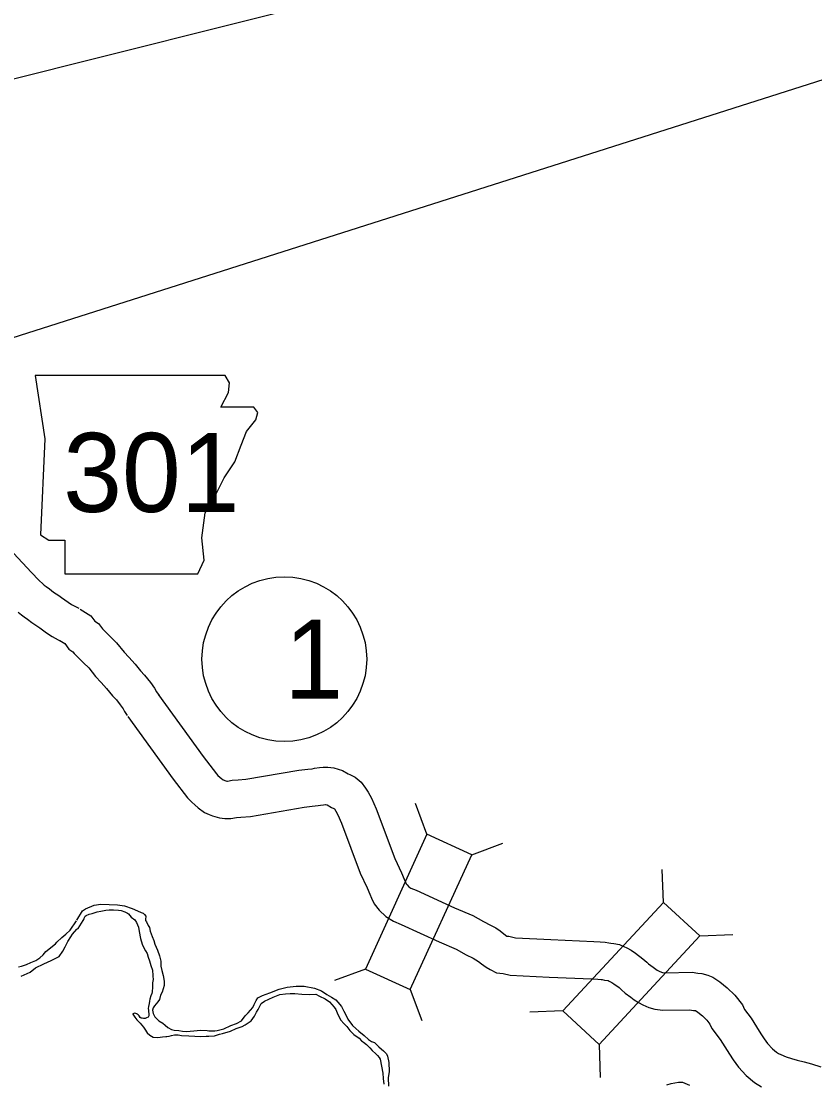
# Model space of a CAD drawing. Extents: x 79818 to 83933, y 50884 to 53307.
# Drawn here: x 81078.5 to 81163.3, y 52994.1 to 53107.7 of the extents above; entities that cross this region are included whole.
import ezdxf

# ---------------------------------------------------------------- set-up
doc = ezdxf.new("R2010")
doc.units = 0
for name, color, linetype in [('Default', 7, 'Continuous'), ('Level 10', 7, 'Continuous'), ('Level 20', 7, 'Continuous'), ('Level 21', 7, 'Continuous'), ('Level 27', 7, 'Continuous'), ('Level 9', 7, 'Continuous')]:
    doc.layers.add(name, color=color, linetype=linetype)

msp = doc.modelspace()

# ---------------------------------------------------------------- linework, layer by layer
at = {"layer": 'Default'}
for p in [(81049.64, 53094.55), (81071.88, 53072.06)]:
    msp.add_line(p, (81483.45, 53203.33), dxfattribs=at)
at = {"layer": 'Level 10'}
for points in [[(81076.23, 53052.4), (81079.64, 53048.78), (81080.41, 53047.98), (81080.86, 53047.53), (81080.99, 53047.43), (81081.18, 53047.28), (81081.55, 53047.04), (81081.99, 53046.69), (81082.54, 53046.33), (81082.83, 53046.13), (81083.54, 53045.62), (81083.89, 53045.38), (81084.68, 53044.96)], [(81078.21, 53044.53), (81078.54, 53044.27), (81078.85, 53044.03), (81079.21, 53043.79), (81079.65, 53043.44), (81080.3, 53043.01), (81080.53, 53042.86), (81081.24, 53042.35), (81081.82, 53041.95), (81082.81, 53041.42)], [(81084.81, 53044.88), (81085.95, 53044.16), (81086.39, 53043.57), (81086.78, 53043.32), (81087.2, 53042.77), (81087.99, 53041.98), (81088.72, 53041.26), (81089.51, 53040.27), (81090.01, 53039.73), (81090.7, 53038.98), (81091.26, 53038.27), (81091.71, 53037.82), (81092.33, 53037.02), (81092.76, 53036.41), (81092.99, 53036.03), (81093.25, 53035.62)], [(81082.67, 53041.5), (81083.17, 53041.18), (81083.62, 53040.58), (81084.03, 53040.32), (81084.18, 53040.13), (81085.18, 53039.14), (81085.74, 53038.58), (81086.48, 53037.65), (81087.08, 53037.02), (81087.65, 53036.39), (81088.27, 53035.6), (81088.7, 53035.17), (81089.11, 53034.65), (81089.41, 53034.22), (81089.58, 53033.93), (81089.86, 53033.49)], [(81093.18, 53035.72), (81097.96, 53029.1), (81099.38, 53027.27), (81099.55, 53027.08), (81099.75, 53026.91), (81099.95, 53026.73), (81100.08, 53026.63), (81100.13, 53026.61), (81100.27, 53026.56), (81100.5, 53026.49), (81100.58, 53026.49), (81101.08, 53026.57), (81101.71, 53026.62), (81102.51, 53026.68), (81108.2, 53027.66), (81109.15, 53027.76), (81109.6, 53027.81), (81109.88, 53027.87), (81110.39, 53027.93), (81110.78, 53027.97), (81111.28, 53027.98), (81111.93, 53027.91), (81112.84, 53027.6), (81113.47, 53027.25), (81113.63, 53027.18), (81114.21, 53026.89), (81114.86, 53026.38), (81115.32, 53025.74), (81115.6, 53025.29), (81115.96, 53024.65), (81116.46, 53023.5), (81118.43, 53018.21), (81119.15, 53016.68), (81119.43, 53015.99), (81119.57, 53015.67), (81119.66, 53015.5), (81119.76, 53015.38), (81119.95, 53015.19), (81120.17, 53015.05), (81120.74, 53014.81), (81124.81, 53012.95), (81126.77, 53012.1), (81127.92, 53011.46), (81128.68, 53011.09), (81129.22, 53010.78), (81129.69, 53010.46), (81130.1, 53010.16), (81130.43, 53009.91), (81130.64, 53009.9), (81131.35, 53009.73), (81135.11, 53009.53), (81139.7, 53009.34), (81140.38, 53009.3), (81140.92, 53009.26), (81141.31, 53009.2), (81141.52, 53009.16), (81141.86, 53009.11), (81142.44, 53009), (81142.93, 53008.79), (81143.22, 53008.64), (81143.68, 53008.4), (81144.15, 53008.08), (81144.96, 53007.49), (81145.37, 53007.11), (81145.56, 53006.93), (81146.03, 53006.6), (81146.35, 53006.36), (81146.48, 53006.27), (81146.68, 53006.17), (81146.92, 53006.06), (81147.03, 53006.03), (81147.34, 53005.99), (81150.21, 53006.04), (81150.81, 53005.94), (81151.26, 53005.91), (81151.89, 53005.72), (81152.42, 53005.51), (81153.18, 53005.01), (81153.97, 53004.37), (81154.76, 53003.61), (81155.58, 53002.57), (81155.8, 53002.07), (81156.53, 53001.12), (81157.08, 53000.21), (81157.56, 52999.47), (81157.92, 52998.93), (81158.27, 52998.43), (81158.79, 52997.87), (81159.21, 52997.51), (81159.45, 52997.36), (81159.67, 52997.27), (81160.27, 52997.02), (81160.83, 52996.83), (81161.43, 52996.66), (81162.19, 52996.48), (81162.98, 52996.26), (81163.95, 52995.93)], [(81089.93, 53033.38), (81094.76, 53026.7), (81096.31, 53024.69), (81096.74, 53024.22), (81097.08, 53023.93), (81097.43, 53023.61), (81098.11, 53023.13), (81098.6, 53022.92), (81098.97, 53022.77), (81099.7, 53022.56), (81100.28, 53022.49), (81100.94, 53022.5), (81101.54, 53022.6), (81102, 53022.63), (81103.01, 53022.7), (81108.76, 53023.7), (81109.6, 53023.79), (81110.24, 53023.86), (81110.52, 53023.92), (81110.84, 53023.96), (81111.03, 53023.98), (81111.07, 53023.98), (81111.2, 53023.93), (81111.67, 53023.67), (81111.92, 53023.56), (81111.99, 53023.52), (81112.15, 53023.26), (81112.37, 53022.86), (81112.76, 53022), (81114.74, 53016.65), (81115.49, 53015.07), (81115.76, 53014.41), (81115.95, 53013.98), (81116.25, 53013.36), (81116.78, 53012.69), (81117.48, 53012.01), (81118.32, 53011.49), (81119.12, 53011.15), (81123.18, 53009.3), (81125, 53008.5), (81126.06, 53007.92), (81126.81, 53007.55), (81127.11, 53007.38), (81127.39, 53007.18), (81127.71, 53006.95), (81128.2, 53006.58), (81128.62, 53006.34), (81129.3, 53005.98), (81130.03, 53005.93), (81130.77, 53005.75), (81134.93, 53005.53), (81139.49, 53005.35), (81140.12, 53005.31), (81140.49, 53005.28), (81140.59, 53005.27), (81140.83, 53005.21), (81141.21, 53005.16), (81141.25, 53005.16), (81141.36, 53005.1), (81141.63, 53004.96), (81141.86, 53004.8), (81142.41, 53004.4), (81142.65, 53004.18), (81143.05, 53003.81), (81143.66, 53003.38), (81144.02, 53003.1), (81144.48, 53002.8), (81144.96, 53002.56), (81145.58, 53002.28), (81146.23, 53002.11), (81147.09, 53001.99), (81149.92, 53002.04), (81150.36, 53001.97), (81150.53, 53001.95), (81150.56, 53001.95), (81150.82, 53001.77), (81151.32, 53001.37), (81151.79, 53000.92), (81152.11, 53000.51), (81152.32, 53000.02), (81153.22, 52998.86), (81153.69, 52998.07), (81154.22, 52997.28), (81154.61, 52996.68), (81155.16, 52995.91), (81156, 52994.99), (81156.86, 52994.25), (81157.61, 52993.8)]]:
    msp.add_lwpolyline(points, dxfattribs=at)
at = {"layer": 'Level 20'}
for p, q in [((81121.87, 53020.8), (81120.64, 53024.1)), ((81126.67, 53018.61), (81129.97, 53019.84)), ((81147.16, 53013.52), (81147.02, 53017.04)), ((81151.03, 53009.93), (81154.55, 53010.07)), ((81115.3, 53006.39), (81112, 53005.15)), ((81120.1, 53004.2), (81121.33, 53000.9)), ((81136.39, 53001.91), (81132.87, 53001.77)), ((81140.26, 52998.32), (81140.39, 52994.8))]:
    msp.add_line(p, q, dxfattribs=at)
for points in [[(81120.1, 53004.2), (81126.67, 53018.61), (81121.87, 53020.8), (81115.3, 53006.39)], [(81147.16, 53013.52), (81136.39, 53001.91), (81140.26, 52998.32), (81151.03, 53009.93)]]:
    msp.add_lwpolyline(points, close=True, dxfattribs=at)
at = {"layer": 'Level 21'}
msp.add_lwpolyline([(81080.02, 53069.85), (81081.04, 53063.08), (81080.59, 53052.81), (81081.49, 53052.25), (81083.18, 53052.25), (81083.18, 53048.64), (81097.39, 53048.64), (81098.07, 53050.11), (81097.84, 53052.48), (81098.18, 53055.18), (81099.42, 53057.33), (81100.21, 53058.91), (81101.34, 53060.6), (81102.01, 53062.4), (81102.58, 53063.87), (81103.59, 53065.11), (81103.82, 53065.9), (81103.37, 53066.46), (81099.87, 53066.46), (81100.66, 53068.04), (81100.77, 53069.06), (81100.31, 53069.84)], close=True, dxfattribs=at)
at = {"layer": 'Level 27'}
msp.add_circle((81106.64, 53039.52), 8.8, dxfattribs=at)
at = {"layer": 'Level 9'}
for points in [[(81084.46, 53011.6), (81085.09, 53012.61), (81085.39, 53012.83), (81086.31, 53013.21), (81087.03, 53013.31), (81087.94, 53013.3), (81088.83, 53013.27), (81089.58, 53013.16), (81090.38, 53012.85), (81090.94, 53012.62), (81091.36, 53012.44), (81091.55, 53012.35), (81091.71, 53012.23), (81091.84, 53012.05), (81091.83, 53011.92), (81091.79, 53011.81), (81091.79, 53011.76), (81091.81, 53011.59), (81091.91, 53011.45), (81092.1, 53011.06), (81092.24, 53010.83), (81092.31, 53010.45), (81092.51, 53009.87), (81092.68, 53009.43), (81092.8, 53009.05), (81093.1, 53008.42), (81093.3, 53007.79), (81093.43, 53007.23), (81093.44, 53006.71), (81093.56, 53006.22), (81093.71, 53005.69), (81093.79, 53005.11), (81093.79, 53004.63), (81093.69, 53004.26), (81093.57, 53003.92), (81093.42, 53003.58), (81093.31, 53003.13), (81093.13, 53002.88), (81092.93, 53002.68), (81092.76, 53002.45), (81092.62, 53002.23), (81092.57, 53002.01), (81092.62, 53001.64), (81092.79, 53001.28), (81093.23, 53000.86), (81093.65, 53000.6), (81093.91, 53000.39), (81094.19, 53000.15), (81094.59, 52999.94), (81094.88, 52999.85), (81095.35, 52999.81), (81095.76, 52999.76), (81096.17, 52999.71), (81096.96, 52999.77), (81097.68, 52999.86), (81098.41, 52999.83), (81098.58, 52999.8), (81099.22, 52999.8), (81099.46, 52999.83), (81100.16, 53000.01), (81100.92, 53000.35), (81101.52, 53000.58), (81102.06, 53000.86), (81102.45, 53001.4), (81102.77, 53001.7), (81103.27, 53002.28), (81103.43, 53002.59), (81103.62, 53003.02), (81103.81, 53003.3), (81104.32, 53003.56), (81105.1, 53003.86), (81106.08, 53004.22), (81106.96, 53004.46), (81107.92, 53004.56), (81108.22, 53004.56), (81108.76, 53004.56), (81109.87, 53004.34), (81110.61, 53004.06), (81111.19, 53003.65), (81111.67, 53003.39), (81112.14, 53003.08), (81112.35, 53002.84), (81112.76, 53002.37), (81112.98, 53001.9), (81113.25, 53001.42), (81113.42, 53001.03), (81113.91, 53000.36), (81114.29, 53000.03), (81114.6, 52999.75), (81115.17, 52999.29), (81115.64, 52998.86), (81115.97, 52998.65), (81116.26, 52998.52), (81116.73, 52998.08), (81117.02, 52997.81), (81117.25, 52997.66), (81117.55, 52997.34), (81117.67, 52997.07), (81117.8, 52996.39), (81117.83, 52995.44)], [(81084.62, 53010.71), (81085.15, 53011.58), (81085.24, 53011.75), (81085.28, 53011.89), (81085.36, 53012.05), (81085.48, 53012.13), (81085.78, 53012.26), (81086.1, 53012.34), (81086.65, 53012.49), (81087.05, 53012.56), (81087.56, 53012.69), (81087.91, 53012.72), (81088.39, 53012.71), (81088.92, 53012.7), (81089.19, 53012.66), (81089.6, 53012.51), (81089.87, 53012.36), (81090, 53012.29), (81090.29, 53011.95), (81090.66, 53011.66), (81090.85, 53011.38), (81091.06, 53010.88), (81091.14, 53010.4), (81091.28, 53009.65), (81091.45, 53009.06), (81091.61, 53008.74), (81091.82, 53008.32), (81091.99, 53008.05), (81092.08, 53007.65), (81092.23, 53007.27), (81092.38, 53006.78), (81092.54, 53006.26), (81092.55, 53006.1), (81092.59, 53005.88), (81092.58, 53005.61), (81092.61, 53005.28), (81092.57, 53004.92), (81092.54, 53004.44), (81092.51, 53003.97), (81092.5, 53003.77), (81092.39, 53003.54), (81092.28, 53003.18), (81092.24, 53002.97), (81092.2, 53002.71), (81092.13, 53002.39), (81092.1, 53002.18), (81092.13, 53001.98), (81092.14, 53001.8), (81092.15, 53001.64), (81092.15, 53001.39), (81092.08, 53001.25), (81091.92, 53001.16), (81091.77, 53001.11), (81091.6, 53001.1), (81091.45, 53001.14), (81091.36, 53001.15), (81091.23, 53001.22), (81091.12, 53001.38), (81091.05, 53001.47), (81091.01, 53001.51), (81090.93, 53001.58), (81090.87, 53001.61), (81090.76, 53001.63), (81090.6, 53001.66), (81090.55, 53001.65), (81090.44, 53001.6), (81090.44, 53001.58), (81090.52, 53001.45), (81090.65, 53001.26), (81090.88, 53000.97), (81091.22, 53000.6), (81091.58, 53000.19), (81091.75, 52999.97), (81091.98, 52999.58), (81092.26, 52999.33), (81092.63, 52999.11), (81093.11, 52999.08), (81093.62, 52999.13), (81093.99, 52999.16), (81094.1, 52999.16), (81094.34, 52999.22), (81094.59, 52999.3), (81094.9, 52999.35), (81095.29, 52999.34), (81095.65, 52999.27), (81096.42, 52999.25), (81097.07, 52999.22), (81097.72, 52999.18), (81098.29, 52999.2), (81098.58, 52999.21), (81099.18, 52999.26), (81099.71, 52999.41), (81100.03, 52999.5), (81100.89, 52999.74), (81101.51, 53000.02), (81102.14, 53000.25), (81102.47, 53000.41), (81103.08, 53000.86), (81103.44, 53001.36), (81103.67, 53001.77), (81103.83, 53002.06)], [(81078.24, 53006.61), (81078.57, 53006.71), (81079.08, 53006.87), (81079.57, 53007.09), (81080.1, 53007.32), (81080.51, 53007.57), (81080.89, 53007.92), (81081.15, 53008.25), (81082.19, 53009.09), (81082.34, 53009.25), (81082.86, 53009.77), (81083.31, 53010.1), (81083.74, 53010.54), (81084.44, 53011.56)], [(81078.53, 53005.63), (81079.49, 53006.07), (81080.06, 53006.53), (81080.93, 53006.96), (81081.72, 53007.32), (81082.57, 53007.74), (81082.99, 53008.29), (81083.23, 53008.75), (81083.52, 53009.32), (81083.83, 53009.84), (81084.02, 53010.12), (81084.46, 53010.65), (81084.62, 53010.71)], [(81103.83, 53002.06), (81104.18, 53002.69), (81104.51, 53002.96), (81105, 53003.17), (81105.44, 53003.38), (81106.15, 53003.67), (81106.78, 53003.74), (81107.28, 53003.79), (81107.76, 53003.77), (81108.51, 53003.71), (81109.28, 53003.67), (81110.01, 53003.69), (81110.41, 53003.48), (81110.99, 53003.19), (81111.48, 53002.88), (81111.96, 53002.33), (81112.13, 53002.06), (81112.29, 53001.7), (81112.51, 53001.25), (81112.68, 53000.94), (81113, 53000.56), (81113.32, 53000.24), (81113.65, 52999.83), (81114.08, 52999.38), (81114.63, 52999), (81114.9, 52998.73), (81115.09, 52998.58), (81115.42, 52998.33), (81115.78, 52997.96), (81116.04, 52997.68), (81116.43, 52997.32), (81116.59, 52997.16), (81116.76, 52996.92), (81116.89, 52996.75), (81117.18, 52995.24), (81117.21, 52994.68), (81117.28, 52994.08)], [(81117.83, 52995.44), (81117.73, 52994.74), (81117.77, 52993.86)], [(81147.49, 52994.02), (81147.98, 52994.14), (81148.76, 52994.28), (81149.18, 52994.28), (81149.94, 52993.98)]]:
    msp.add_lwpolyline(points, dxfattribs=at)

# ---------------------------------------------------------------- texts
at = {"layer": 'Level 21'}
msp.add_text('301', height=8.448, dxfattribs=at).set_placement((81083.01, 53055.26))
at = {"layer": 'Level 27'}
msp.add_text('1', height=8.45, dxfattribs=at).set_placement((81106.64, 53035.3))

doc.saveas('drawing.dxf')
